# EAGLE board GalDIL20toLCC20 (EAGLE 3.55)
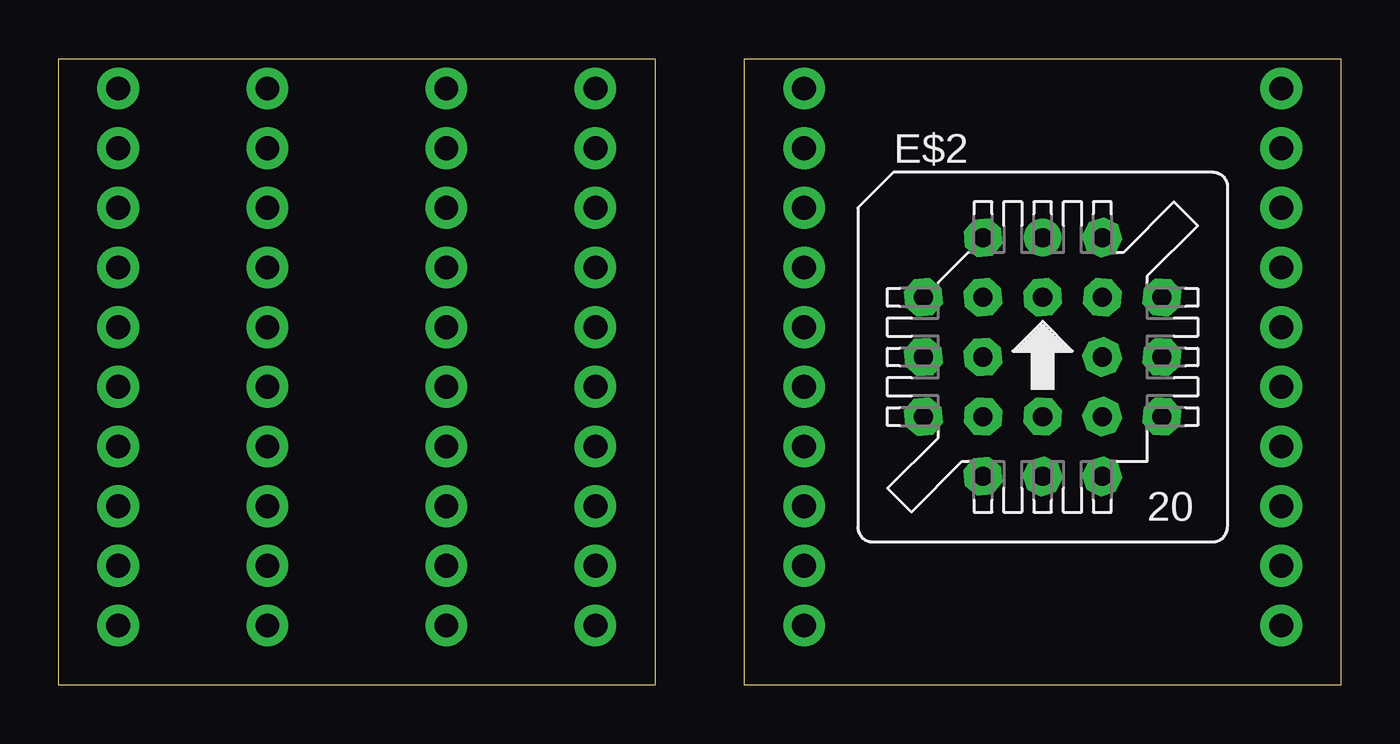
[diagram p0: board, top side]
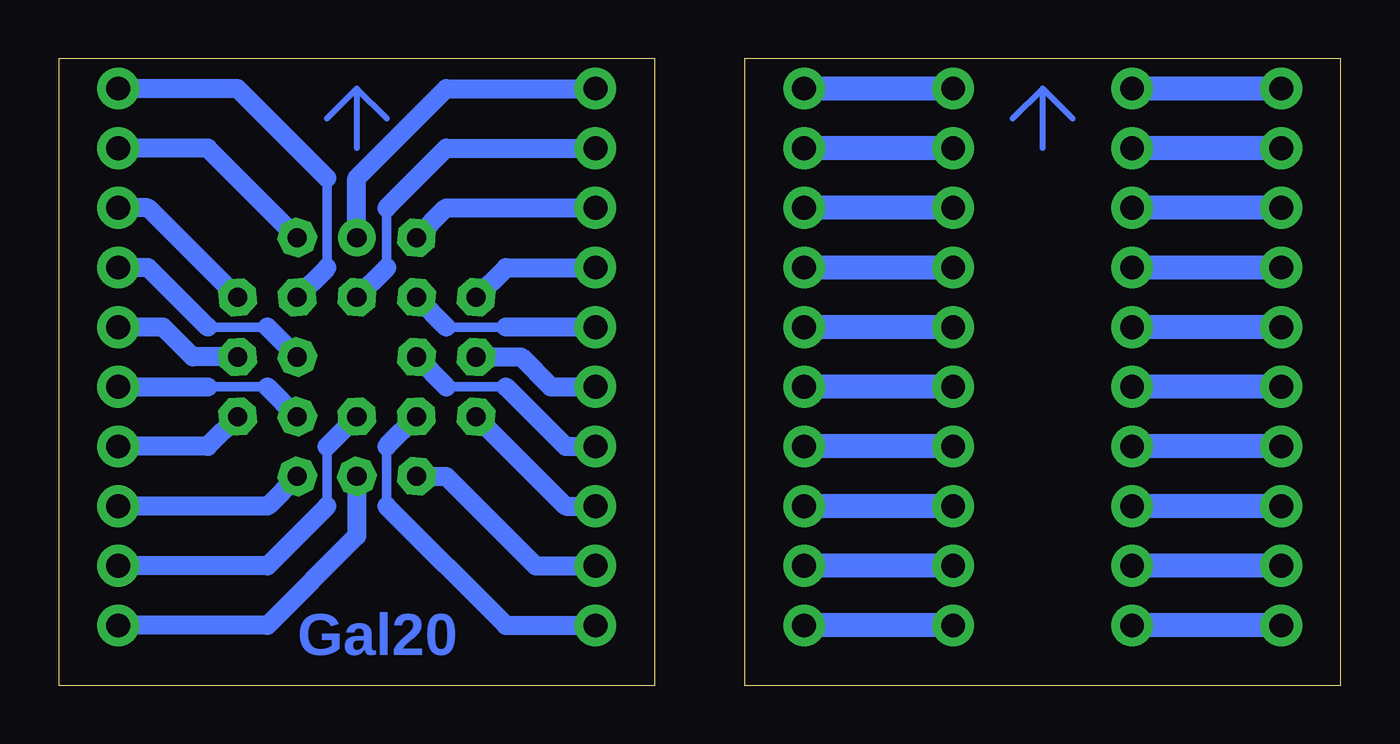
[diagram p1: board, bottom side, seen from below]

Size 54.61 x 26.67 mm. Coordinates in mm from the lower left corner, seen from the top.
Outline: 25.4,26.67 25.4,0 0,0 0,26.67 25.4,26.67
Outline: 29.21,26.67 54.61,26.67 54.61,0 29.21,0 29.21,26.67
Copper layers used: Bottom

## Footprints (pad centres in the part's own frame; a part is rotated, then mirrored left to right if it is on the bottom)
0 = drill 0.813 pad 1.6 round:  0,5.08 | drill 0.813 pad 1.6 octagon:  0,2.54;  -2.54,5.08;  -5.08,2.54;  -2.54,2.54;  -5.08,0;  -2.54,0;  -5.08,-2.54;  -2.54,-5.08;  -2.54,-2.54;  0,-5.08;  0,-2.54;  2.54,-5.08;  5.08,-2.54;  2.54,-2.54;  5.08,0;  2.54,0;  5.08,2.54;  2.54,5.08;  2.54,2.54
AD10 = drill 1.016 pad 1.778 round:  0,0

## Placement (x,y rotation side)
E$2  [0]  41.91,13.97 0 top
E$9  [AD10]  2.54,25.4 0 top
E$10  [AD10]  2.54,22.86 0 top
E$11  [AD10]  2.54,20.32 0 top
E$12  [AD10]  2.54,17.78 0 top
E$13  [AD10]  2.54,15.24 0 top
E$14  [AD10]  2.54,12.7 0 top
E$15  [AD10]  2.54,10.16 0 top
E$16  [AD10]  2.54,7.62 0 top
E$17  [AD10]  2.54,5.08 0 top
E$18  [AD10]  2.54,2.54 0 top
E$25  [AD10]  22.86,25.4 0 top
E$26  [AD10]  22.86,22.86 0 top
E$27  [AD10]  22.86,20.32 0 top
E$28  [AD10]  22.86,17.78 0 top
E$29  [AD10]  22.86,15.24 0 top
E$30  [AD10]  22.86,12.7 0 top
E$31  [AD10]  22.86,10.16 0 top
E$32  [AD10]  22.86,7.62 0 top
E$33  [AD10]  22.86,5.08 0 top
E$34  [AD10]  22.86,2.54 0 top
E$41  [AD10]  8.89,25.4 0 top
E$42  [AD10]  8.89,22.86 0 top
E$43  [AD10]  8.89,20.32 0 top
E$44  [AD10]  8.89,17.78 0 top
E$45  [AD10]  8.89,15.24 0 top
E$46  [AD10]  8.89,12.7 0 top
E$47  [AD10]  8.89,10.16 0 top
E$48  [AD10]  8.89,7.62 0 top
E$49  [AD10]  8.89,5.08 0 top
E$50  [AD10]  8.89,2.54 0 top
E$57  [AD10]  16.51,25.4 0 top
E$58  [AD10]  16.51,22.86 0 top
E$59  [AD10]  16.51,20.32 0 top
E$60  [AD10]  16.51,17.78 0 top
E$61  [AD10]  16.51,15.24 0 top
E$62  [AD10]  16.51,12.7 0 top
E$63  [AD10]  16.51,10.16 0 top
E$64  [AD10]  16.51,7.62 0 top
E$65  [AD10]  16.51,5.08 0 top
E$66  [AD10]  16.51,2.54 0 top
E$72  [AD10]  31.75,25.4 0 top
E$73  [AD10]  31.75,22.86 0 top
E$74  [AD10]  31.75,20.32 0 top
E$75  [AD10]  31.75,17.78 0 top
E$76  [AD10]  31.75,15.24 0 top
E$77  [AD10]  31.75,12.7 0 top
E$78  [AD10]  31.75,10.16 0 top
E$79  [AD10]  31.75,7.62 0 top
E$80  [AD10]  31.75,5.08 0 top
E$81  [AD10]  31.75,2.54 0 top
E$88  [AD10]  52.07,25.4 0 top
E$89  [AD10]  52.07,22.86 0 top
E$90  [AD10]  52.07,20.32 0 top
E$91  [AD10]  52.07,17.78 0 top
E$92  [AD10]  52.07,15.24 0 top
E$93  [AD10]  52.07,12.7 0 top
E$94  [AD10]  52.07,10.16 0 top
E$95  [AD10]  52.07,7.62 0 top
E$96  [AD10]  52.07,5.08 0 top
E$97  [AD10]  52.07,2.54 0 top

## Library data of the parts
E$2 = PLCCPACK
E$9-E$18 E$25-E$34 E$41-E$50 E$57-E$66 E$72-E$81 E$88-E$97 = holgnorm

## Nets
S$1: E$2. E$72.
S$2: E$2. E$73.
S$3: E$2. E$74.
S$4: E$2. E$75.
S$5: E$2. E$76.
S$6: E$2. E$77.
S$7: E$9. E$41.
S$8: E$10. E$42.
S$9: E$11. E$43.
S$10: E$12. E$44.
S$11: E$13. E$45.
S$12: E$14. E$46.
S$13: E$15. E$47.
S$14: E$16. E$48.
S$15: E$17. E$49.
S$16: E$18. E$50.
S$17: E$2. E$78.
S$18: E$2. E$79.
S$19: E$2. E$80.
S$20: E$2. E$81.
S$21: E$2. E$97.
S$22: E$2. E$96.
S$23: E$25. E$57.
S$24: E$26. E$58.
S$25: E$27. E$59.
S$26: E$28. E$60.
S$27: E$29. E$61.
S$28: E$30. E$62.
S$29: E$31. E$63.
S$30: E$32. E$64.
S$31: E$33. E$65.
S$32: E$34. E$66.
S$33: E$2. E$95.
S$34: E$2. E$94.
S$35: E$2. E$93.
S$36: E$2. E$92.
S$37: E$2. E$91.
S$38: E$2. E$90.
S$39: E$2. E$89.
S$40: E$2. E$88.

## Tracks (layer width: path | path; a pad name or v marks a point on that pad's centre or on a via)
S$1
  Bottom 0.813: 41.91,19.05 41.91,21.59 38.1,25.4 E$72.
S$2
  Bottom 0.406: 40.64,17.78 40.64,20.32
  Bottom 0.813: 41.91,16.51 40.64,17.78 | 40.64,20.32 38.1,22.86 E$73.
S$3
  Bottom 0.813: 39.37,19.05 38.1,20.32 E$74.
S$4
  Bottom 0.813: 36.83,16.51 35.56,17.78 E$75.
S$5
  Bottom 0.406: 38.1,15.24 35.56,15.24
  Bottom 0.813: 39.37,16.51 38.1,15.24 | E$76. 35.56,15.24
S$6
  Bottom 0.813: 36.83,13.97 34.92,13.97 33.65,12.7 E$77.
S$7
  Bottom 1.016: E$9. E$41.
S$8
  Bottom 1.016: E$10. E$42.
S$9
  Bottom 1.016: E$11. E$43.
S$10
  Bottom 1.016: E$12. E$44.
S$11
  Bottom 1.016: E$13. E$45.
S$12
  Bottom 1.016: E$14. E$46.
S$13
  Bottom 1.016: E$15. E$47.
S$14
  Bottom 1.016: E$16. E$48.
S$15
  Bottom 1.016: E$17. E$49.
S$16
  Bottom 1.016: E$18. E$50.
S$17
  Bottom 0.406: 38.1,12.7 35.56,12.7
  Bottom 0.813: 39.37,13.97 38.1,12.7 | 35.56,12.7 33.02,10.16 E$78.
S$18
  Bottom 0.813: 36.83,11.43 33.02,7.62 E$79.
S$19
  Bottom 0.813: 39.37,8.89 38.1,8.89 34.29,5.08 E$80.
S$20
  Bottom 0.406: 40.64,10.16 40.64,7.62
  Bottom 0.813: 39.37,11.43 40.64,10.16 | 40.64,7.62 35.56,2.54 E$81.
S$21
  Bottom 0.813: 41.91,8.89 41.91,6.35 45.72,2.54 E$97.
S$22
  Bottom 0.406: 43.18,10.16 43.18,7.62
  Bottom 0.813: 41.91,11.43 43.18,10.16 | 43.18,7.62 45.72,5.08 E$96.
S$23
  Bottom 1.016: E$57. E$25.
S$24
  Bottom 1.016: E$58. E$26.
S$25
  Bottom 1.016: E$59. E$27.
S$26
  Bottom 1.016: E$60. E$28.
S$27
  Bottom 1.016: E$61. E$29.
S$28
  Bottom 1.016: E$62. E$30.
S$29
  Bottom 1.016: E$63. E$31.
S$30
  Bottom 1.016: E$64. E$32.
S$31
  Bottom 1.016: E$65. E$33.
S$32
  Bottom 1.016: E$66. E$34.
S$33
  Bottom 0.813: 44.45,8.89 45.72,7.62 E$95.
S$34
  Bottom 0.813: 46.99,11.43 48.26,10.16 E$94.
S$35
  Bottom 0.406: 45.72,12.7 48.26,12.7
  Bottom 0.813: 44.45,11.43 45.72,12.7 | E$93. 48.26,12.7
S$36
  Bottom 0.813: 46.99,13.97 48.89,13.97 50.16,15.24 E$92.
S$37
  Bottom 0.406: 45.72,15.24 48.26,15.24
  Bottom 0.813: 44.45,13.97 45.72,15.24 | 48.26,15.24 50.8,17.78 E$91.
S$38
  Bottom 0.813: 46.99,16.51 50.8,20.32 E$90.
S$39
  Bottom 0.813: 44.45,19.05 48.26,22.86 E$89.
S$40
  Bottom 0.406: 43.18,17.78 43.18,21.59
  Bottom 0.813: E$2. 43.18,17.78 | 43.18,21.59 46.99,25.4 E$88.
S$65
  Bottom 0.254: 41.91,25.4 41.91,22.86 | 40.64,24.13 41.91,25.4 | 41.91,25.4 43.18,24.13
S$66
  Bottom 0.254: 12.7,22.86 12.7,25.4 | 12.7,25.4 11.43,24.13 | 12.7,25.4 13.97,24.13

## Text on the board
Bottom: Gal20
